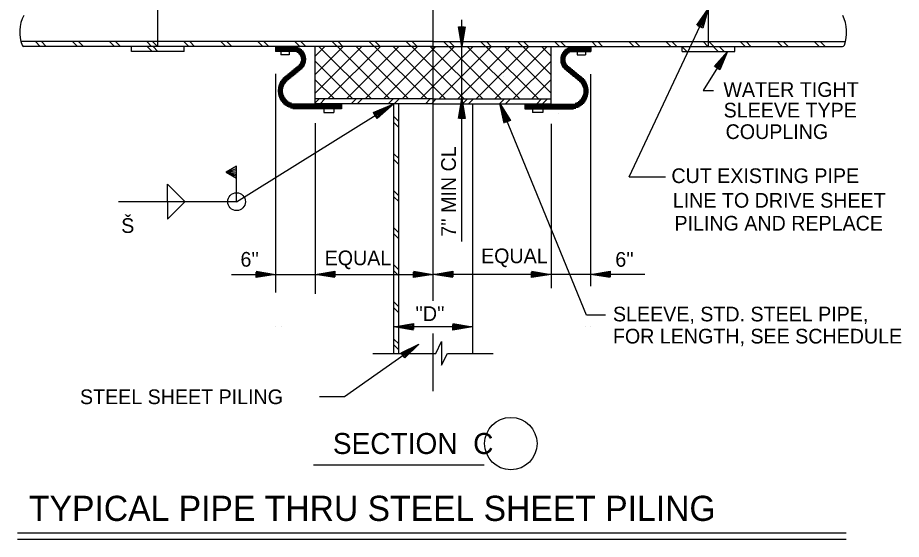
# Model space of a CAD drawing. Extents: x 22411.4 to 22495.4, y 22369.6 to 22415.
# Drawn here: x 22451.27 to 22462.5, y 22382.35 to 22388.98 of the extents above; entities that cross this region are included whole.
import ezdxf

# ---------------------------------------------------------------- set-up
doc = ezdxf.new("R2010")
doc.units = 0
for name, color, linetype in [('Level 1', 7, 'Continuous'), ('Level 10', 7, 'Continuous'), ('Level 2', 7, 'Continuous'), ('Level 3', 7, 'Continuous'), ('Level 4', 7, 'Continuous'), ('Level 8', 7, 'Continuous')]:
    doc.layers.add(name, color=color, linetype=linetype)

msp = doc.modelspace()

# ---------------------------------------------------------------- linework, layer by layer
at = {"layer": 'Level 1'}
for p, q in [((22456.549, 22385.383), (22456.549, 22394.627)), ((22456.914, 22388.617), (22456.914, 22388.955)), ((22456.914, 22388.686), (22456.914, 22388.686)), ((22456.914, 22387.95), (22456.914, 22388.617)), ((22456.914, 22388.617), (22456.914, 22388.617)), ((22454.614, 22388.555), (22454.614, 22388.512)), ((22454.718, 22388.512), (22454.614, 22388.512)), ((22454.718, 22388.555), (22454.718, 22388.512)), ((22458.381, 22388.555), (22458.381, 22388.512)), ((22458.381, 22388.512), (22458.485, 22388.512)), ((22458.485, 22388.555), (22458.485, 22388.512)), ((22460.252, 22388.496), (22460.252, 22388.496)), ((22460.289, 22388.555), (22460.289, 22388.555)), ((22454.547, 22388.268), (22454.547, 22385.49)), ((22455.996, 22388.26), (22455.996, 22388.26)), ((22457.441, 22388.23), (22457.441, 22388.23)), ((22458.549, 22388.265), (22458.549, 22385.57)), ((22456.049, 22387.888), (22456.049, 22387.888)), ((22456.914, 22386.137), (22456.914, 22387.95)), ((22456.914, 22387.95), (22456.914, 22387.95)), ((22455.158, 22387.826), (22455.158, 22387.779)), ((22455.158, 22387.779), (22455.286, 22387.779)), ((22455.286, 22387.826), (22455.286, 22387.779)), ((22456.914, 22387.881), (22456.914, 22387.881)), ((22457.417, 22387.878), (22457.417, 22387.878)), ((22457.813, 22387.826), (22457.813, 22387.779)), ((22457.941, 22387.779), (22457.813, 22387.779)), ((22457.941, 22387.826), (22457.941, 22387.779)), ((22458.136, 22387.834), (22458.136, 22387.834)), ((22458.144, 22387.765), (22458.144, 22387.765)), ((22455.049, 22387.643), (22455.049, 22385.472)), ((22458.049, 22387.635), (22458.049, 22385.543)), ((22453.984, 22385.719), (22454.547, 22385.719)), ((22454.547, 22385.719), (22455.049, 22385.719)), ((22455.049, 22385.719), (22455.049, 22385.719)), ((22455.049, 22385.719), (22456.549, 22385.719)), ((22455.119, 22385.719), (22455.119, 22385.719)), ((22456.48, 22385.719), (22456.48, 22385.719)), ((22456.549, 22385.719), (22456.549, 22385.719)), ((22456.549, 22385.719), (22456.549, 22385.719)), ((22458.049, 22385.719), (22456.549, 22385.719)), ((22456.619, 22385.719), (22456.619, 22385.719)), ((22457.98, 22385.719), (22457.98, 22385.719)), ((22458.049, 22385.719), (22458.049, 22385.719)), ((22458.549, 22385.719), (22458.049, 22385.719)), ((22459.24, 22385.719), (22458.549, 22385.719)), ((22454.547, 22385.053), (22454.547, 22385.053)), ((22454.617, 22385.053), (22454.617, 22385.053)), ((22457.049, 22385.053), (22456.049, 22385.053)), ((22456.48, 22385.053), (22456.48, 22385.053)), ((22456.549, 22385.053), (22456.549, 22385.053)), ((22456.549, 22385.053), (22456.549, 22385.053)), ((22456.549, 22384.235), (22456.549, 22384.97)), ((22456.619, 22385.053), (22456.619, 22385.053)), ((22458.48, 22385.053), (22458.48, 22385.053)), ((22458.549, 22385.053), (22458.549, 22385.053)), ((22456.312, 22384.794), (22456.312, 22384.794)), ((22456.369, 22384.834), (22456.369, 22384.834)), ((22455.783, 22384.715), (22456.581, 22384.715)), ((22456.731, 22384.715), (22457.311, 22384.715))]:
    msp.add_line(p, q, dxfattribs=at)
for points in [[(22456.955, 22388.866), (22456.914, 22388.617), (22456.873, 22388.866), (22456.943, 22388.866), (22456.914, 22388.686), (22456.886, 22388.856), (22456.931, 22388.856), (22456.914, 22388.753), (22456.899, 22388.845), (22456.918, 22388.845), (22456.914, 22388.822)], [(22456.873, 22387.701), (22456.914, 22387.95), (22456.955, 22387.701), (22456.885, 22387.701), (22456.914, 22387.881), (22456.942, 22387.712), (22456.897, 22387.712), (22456.914, 22387.814), (22456.929, 22387.722), (22456.91, 22387.722), (22456.914, 22387.745)], [(22456.581, 22384.715), (22456.656, 22384.865), (22456.656, 22384.565), (22456.731, 22384.715)]]:
    msp.add_lwpolyline(points, dxfattribs=at)
for centre, radius, start, end in [((22451.774, 22388.798), 0.48, 153.3929, 200.1919), ((22461.325, 22388.798), 0.48, 339.8081, 26.6071), ((22451.346, 22388.641), 0.0235, 200.3155, 270), ((22461.753, 22388.641), 0.0235, 270, 339.6845)]:
    msp.add_arc(centre, radius, start, end, dxfattribs=at)
at = {"layer": 'Level 10'}
for p, q in [((22454.051, 22386.644), (22456.049, 22387.888)), ((22456.049, 22387.888), (22456.049, 22387.888)), ((22455.983, 22387.847), (22455.983, 22387.847)), ((22454.051, 22387.094), (22453.92, 22387.019)), ((22453.92, 22387.019), (22454.051, 22387.066)), ((22453.92, 22387.019), (22454.051, 22387.04)), ((22453.92, 22387.019), (22454.05, 22386.944)), ((22453.92, 22387.019), (22454.043, 22387.012)), ((22453.92, 22387.019), (22454.048, 22386.989)), ((22453.92, 22387.019), (22454.051, 22386.968)), ((22454.051, 22386.644), (22454.051, 22387.094)), ((22453.172, 22386.866), (22453.395, 22386.643)), ((22453.172, 22386.641), (22453.172, 22386.866)), ((22454.051, 22386.644), (22452.55, 22386.644)), ((22453.172, 22386.646), (22453.172, 22386.421)), ((22453.172, 22386.421), (22453.395, 22386.645)), ((22455.029, 22383.3), (22457.199, 22383.3)), ((22451.268, 22382.434), (22461.797, 22382.434)), ((22451.268, 22382.351), (22461.797, 22382.351))]:
    msp.add_line(p, q, dxfattribs=at)
msp.add_lwpolyline([(22455.787, 22387.779), (22456.049, 22387.888), (22455.836, 22387.7), (22455.794, 22387.768), (22455.983, 22387.847), (22455.838, 22387.719), (22455.811, 22387.763), (22455.92, 22387.807), (22455.84, 22387.738), (22455.829, 22387.756), (22455.853, 22387.766)], dxfattribs=at)
msp.add_circle((22454.051, 22386.644), 0.113, dxfattribs=at)
at = {"layer": 'Level 2'}
for p, q in [((22453.049, 22388.617), (22453.049, 22389.409)), ((22460.049, 22388.617), (22460.049, 22389.409)), ((22459.039, 22386.96), (22460.044, 22389.095)), ((22456.549, 22388.68), (22451.309, 22388.68)), ((22456.549, 22388.68), (22461.79, 22388.68)), ((22456.549, 22388.617), (22451.346, 22388.617)), ((22452.716, 22388.555), (22452.716, 22388.617)), ((22453.383, 22388.555), (22453.383, 22388.617)), ((22454.546, 22388.617), (22454.546, 22388.555)), ((22454.707, 22388.622), (22454.707, 22388.617)), ((22455.049, 22387.888), (22455.049, 22388.617)), ((22456.549, 22388.617), (22461.753, 22388.617)), ((22458.049, 22387.888), (22458.049, 22388.617)), ((22458.553, 22388.617), (22458.553, 22388.555)), ((22459.716, 22388.555), (22459.716, 22388.617)), ((22460.383, 22388.555), (22460.383, 22388.617)), ((22453.383, 22388.555), (22452.716, 22388.555)), ((22454.811, 22388.555), (22454.546, 22388.555)), ((22458.288, 22388.555), (22458.553, 22388.555)), ((22459.716, 22388.555), (22460.383, 22388.555)), ((22460.289, 22388.555), (22459.979, 22388.056)), ((22459.979, 22388.056), (22460.111, 22388.056)), ((22456.549, 22387.95), (22455.049, 22387.95)), ((22456.549, 22387.888), (22455.049, 22387.888)), ((22455.384, 22387.888), (22455.384, 22387.826)), ((22456.049, 22384.715), (22456.049, 22387.888)), ((22456.112, 22384.715), (22456.112, 22387.888)), ((22456.549, 22387.95), (22458.049, 22387.95)), ((22456.549, 22387.888), (22458.049, 22387.888)), ((22457.049, 22387.888), (22457.049, 22384.715)), ((22457.715, 22387.888), (22457.715, 22387.826)), ((22455.384, 22387.826), (22454.765, 22387.826)), ((22457.715, 22387.826), (22458.334, 22387.826)), ((22459.039, 22386.96), (22459.504, 22386.96))]:
    msp.add_line(p, q, dxfattribs=at)
for points in [[(22459.9, 22388.887), (22460.044, 22389.095), (22459.975, 22388.852), (22459.911, 22388.882), (22460.014, 22389.032), (22459.967, 22388.867), (22459.926, 22388.886), (22459.986, 22388.972), (22459.96, 22388.882), (22459.943, 22388.89), (22459.956, 22388.909)], [(22454.797, 22388.615), (22454.549, 22388.615)], [(22454.831, 22388.605), (22454.549, 22388.605)], [(22454.852, 22388.594), (22454.549, 22388.594)], [(22454.867, 22388.584), (22454.549, 22388.584)], [(22454.88, 22388.573), (22454.549, 22388.573)], [(22454.89, 22388.563), (22454.549, 22388.563)], [(22458.209, 22388.563), (22458.549, 22388.563)], [(22458.219, 22388.573), (22458.549, 22388.573)], [(22458.232, 22388.584), (22458.549, 22388.584)], [(22458.247, 22388.594), (22458.549, 22388.594)], [(22458.267, 22388.605), (22458.549, 22388.605)], [(22458.302, 22388.615), (22458.549, 22388.615)], [(22454.899, 22388.552), (22454.79, 22388.552)], [(22454.906, 22388.542), (22454.817, 22388.542)], [(22454.912, 22388.532), (22454.832, 22388.532)], [(22454.917, 22388.521), (22454.843, 22388.521)], [(22454.922, 22388.511), (22454.852, 22388.511)], [(22454.925, 22388.5), (22454.858, 22388.5)], [(22454.928, 22388.49), (22454.863, 22388.49)], [(22454.93, 22388.48), (22454.867, 22388.48)], [(22454.932, 22388.469), (22454.869, 22388.469)], [(22454.933, 22388.459), (22454.87, 22388.459)], [(22458.166, 22388.459), (22458.229, 22388.459)], [(22458.167, 22388.469), (22458.23, 22388.469)], [(22458.168, 22388.48), (22458.232, 22388.48)], [(22458.171, 22388.49), (22458.236, 22388.49)], [(22458.173, 22388.5), (22458.241, 22388.5)], [(22458.177, 22388.511), (22458.247, 22388.511)], [(22458.181, 22388.521), (22458.256, 22388.521)], [(22458.187, 22388.532), (22458.266, 22388.532)], [(22458.193, 22388.542), (22458.282, 22388.542)], [(22458.2, 22388.552), (22458.308, 22388.552)], [(22460.122, 22388.365), (22460.289, 22388.555), (22460.192, 22388.321), (22460.132, 22388.358), (22460.252, 22388.496), (22460.187, 22388.337), (22460.148, 22388.361), (22460.217, 22388.439), (22460.181, 22388.353), (22460.165, 22388.363), (22460.18, 22388.38)], [(22454.894, 22388.344), (22454.8, 22388.344)], [(22454.902, 22388.355), (22454.813, 22388.355)], [(22454.909, 22388.365), (22454.825, 22388.365)], [(22454.915, 22388.375), (22454.838, 22388.375)], [(22454.92, 22388.386), (22454.847, 22388.386)], [(22454.924, 22388.396), (22454.855, 22388.396)], [(22454.927, 22388.407), (22454.86, 22388.407)], [(22454.929, 22388.417), (22454.865, 22388.417)], [(22454.931, 22388.427), (22454.868, 22388.427)], [(22454.933, 22388.448), (22454.87, 22388.448)], [(22454.932, 22388.438), (22454.87, 22388.438)], [(22458.166, 22388.448), (22458.228, 22388.448)], [(22458.166, 22388.438), (22458.229, 22388.438)], [(22458.168, 22388.427), (22458.231, 22388.427)], [(22458.169, 22388.417), (22458.234, 22388.417)], [(22458.172, 22388.407), (22458.238, 22388.407)], [(22458.175, 22388.396), (22458.244, 22388.396)], [(22458.179, 22388.386), (22458.251, 22388.386)], [(22458.184, 22388.375), (22458.261, 22388.375)], [(22458.19, 22388.365), (22458.273, 22388.365)], [(22458.197, 22388.355), (22458.286, 22388.355)], [(22458.205, 22388.344), (22458.299, 22388.344)], [(22454.758, 22388.23), (22454.66, 22388.23)], [(22454.771, 22388.24), (22454.672, 22388.24)], [(22454.784, 22388.25), (22454.685, 22388.25)], [(22454.797, 22388.261), (22454.698, 22388.261)], [(22454.809, 22388.271), (22454.711, 22388.271)], [(22454.822, 22388.282), (22454.723, 22388.282)], [(22454.835, 22388.292), (22454.736, 22388.292)], [(22454.848, 22388.302), (22454.749, 22388.302)], [(22454.86, 22388.313), (22454.762, 22388.313)], [(22454.873, 22388.323), (22454.774, 22388.323)], [(22454.885, 22388.334), (22454.787, 22388.334)], [(22458.214, 22388.334), (22458.312, 22388.334)], [(22458.226, 22388.323), (22458.325, 22388.323)], [(22458.238, 22388.313), (22458.337, 22388.313)], [(22458.251, 22388.302), (22458.35, 22388.302)], [(22458.264, 22388.292), (22458.363, 22388.292)], [(22458.277, 22388.282), (22458.376, 22388.282)], [(22458.289, 22388.271), (22458.388, 22388.271)], [(22458.302, 22388.261), (22458.401, 22388.261)], [(22458.315, 22388.25), (22458.414, 22388.25)], [(22458.328, 22388.24), (22458.427, 22388.24)], [(22458.341, 22388.23), (22458.439, 22388.23)], [(22454.65, 22388.115), (22454.584, 22388.115)], [(22454.655, 22388.125), (22454.588, 22388.125)], [(22454.661, 22388.136), (22454.591, 22388.136)], [(22454.667, 22388.146), (22454.596, 22388.146)], [(22454.675, 22388.157), (22454.601, 22388.157)], [(22454.684, 22388.167), (22454.606, 22388.167)], [(22454.695, 22388.177), (22454.613, 22388.177)], [(22454.707, 22388.188), (22454.62, 22388.188)], [(22454.72, 22388.198), (22454.628, 22388.198)], [(22454.733, 22388.209), (22454.637, 22388.209)], [(22454.746, 22388.219), (22454.648, 22388.219)], [(22458.353, 22388.219), (22458.451, 22388.219)], [(22458.366, 22388.209), (22458.462, 22388.209)], [(22458.379, 22388.198), (22458.471, 22388.198)], [(22458.392, 22388.188), (22458.479, 22388.188)], [(22458.404, 22388.177), (22458.486, 22388.177)], [(22458.415, 22388.167), (22458.492, 22388.167)], [(22458.424, 22388.157), (22458.498, 22388.157)], [(22458.432, 22388.146), (22458.503, 22388.146)], [(22458.438, 22388.136), (22458.507, 22388.136)], [(22458.444, 22388.125), (22458.511, 22388.125)], [(22458.449, 22388.115), (22458.515, 22388.115)], [(22454.639, 22388.063), (22454.576, 22388.063)], [(22454.638, 22388.052), (22454.576, 22388.052)], [(22454.639, 22388.042), (22454.576, 22388.042)], [(22454.64, 22388.073), (22454.577, 22388.073)], [(22454.639, 22388.032), (22454.577, 22388.032)], [(22454.641, 22388.084), (22454.578, 22388.084)], [(22454.641, 22388.021), (22454.578, 22388.021)], [(22454.644, 22388.094), (22454.58, 22388.094)], [(22454.643, 22388.011), (22454.58, 22388.011)], [(22454.647, 22388.105), (22454.582, 22388.105)], [(22454.647, 22388), (22454.582, 22388)], [(22458.452, 22388.105), (22458.517, 22388.105)], [(22458.452, 22388), (22458.517, 22388)], [(22458.455, 22388.094), (22458.519, 22388.094)], [(22458.455, 22388.011), (22458.519, 22388.011)], [(22458.458, 22388.084), (22458.521, 22388.084)], [(22458.458, 22388.021), (22458.521, 22388.021)], [(22458.459, 22388.073), (22458.522, 22388.073)], [(22458.459, 22388.032), (22458.522, 22388.032)], [(22458.46, 22388.063), (22458.523, 22388.063)], [(22458.46, 22388.042), (22458.523, 22388.042)], [(22458.461, 22388.052), (22458.523, 22388.052)], [(22454.65, 22387.99), (22454.584, 22387.99)], [(22454.655, 22387.98), (22454.588, 22387.98)], [(22454.66, 22387.969), (22454.591, 22387.969)], [(22454.667, 22387.959), (22454.596, 22387.959)], [(22454.675, 22387.948), (22454.601, 22387.948)], [(22454.684, 22387.938), (22454.606, 22387.938)], [(22454.695, 22387.927), (22454.613, 22387.927)], [(22454.708, 22387.917), (22454.62, 22387.917)], [(22454.724, 22387.907), (22454.628, 22387.907)], [(22454.747, 22387.896), (22454.637, 22387.896)], [(22458.741, 22385.202), (22458.496, 22385.202), (22457.397, 22387.891)], [(22457.453, 22387.644), (22457.397, 22387.891), (22457.53, 22387.676), (22457.464, 22387.649), (22457.423, 22387.827), (22457.513, 22387.68), (22457.471, 22387.663), (22457.449, 22387.765), (22457.497, 22387.685), (22457.48, 22387.678), (22457.475, 22387.701)], [(22458.352, 22387.896), (22458.462, 22387.896)], [(22458.375, 22387.907), (22458.471, 22387.907)], [(22458.391, 22387.917), (22458.479, 22387.917)], [(22458.404, 22387.927), (22458.486, 22387.927)], [(22458.415, 22387.938), (22458.493, 22387.938)], [(22458.424, 22387.948), (22458.498, 22387.948)], [(22458.432, 22387.959), (22458.503, 22387.959)], [(22458.438, 22387.969), (22458.508, 22387.969)], [(22458.444, 22387.98), (22458.511, 22387.98)], [(22458.449, 22387.99), (22458.515, 22387.99)], [(22455.383, 22387.886), (22454.647, 22387.886)], [(22455.383, 22387.875), (22454.659, 22387.875)], [(22455.383, 22387.865), (22454.673, 22387.865)], [(22455.383, 22387.855), (22454.689, 22387.855)], [(22455.383, 22387.844), (22454.709, 22387.844)], [(22455.383, 22387.834), (22454.736, 22387.834)], [(22457.716, 22387.886), (22458.451, 22387.886)], [(22457.716, 22387.875), (22458.44, 22387.875)], [(22457.716, 22387.865), (22458.426, 22387.865)], [(22457.716, 22387.855), (22458.41, 22387.855)], [(22457.716, 22387.844), (22458.39, 22387.844)], [(22457.716, 22387.834), (22458.363, 22387.834)], [(22454.298, 22385.761), (22454.547, 22385.719), (22454.298, 22385.678), (22454.298, 22385.749), (22454.478, 22385.719), (22454.309, 22385.691), (22454.309, 22385.737), (22454.411, 22385.719), (22454.319, 22385.705), (22454.319, 22385.723), (22454.342, 22385.719)], [(22455.299, 22385.678), (22455.049, 22385.719), (22455.299, 22385.761), (22455.299, 22385.69), (22455.119, 22385.719), (22455.288, 22385.747), (22455.288, 22385.702), (22455.185, 22385.719), (22455.277, 22385.734), (22455.277, 22385.715), (22455.255, 22385.719)], [(22456.3, 22385.761), (22456.549, 22385.719), (22456.3, 22385.678), (22456.3, 22385.749), (22456.48, 22385.719), (22456.311, 22385.691), (22456.311, 22385.737), (22456.413, 22385.719), (22456.321, 22385.705), (22456.321, 22385.723), (22456.344, 22385.719)], [(22456.799, 22385.678), (22456.549, 22385.719), (22456.799, 22385.761), (22456.799, 22385.69), (22456.619, 22385.719), (22456.788, 22385.747), (22456.788, 22385.702), (22456.685, 22385.719), (22456.777, 22385.734), (22456.777, 22385.715), (22456.755, 22385.719)], [(22457.8, 22385.761), (22458.049, 22385.719), (22457.8, 22385.678), (22457.8, 22385.749), (22457.98, 22385.719), (22457.811, 22385.691), (22457.811, 22385.737), (22457.913, 22385.719), (22457.821, 22385.705), (22457.821, 22385.723), (22457.844, 22385.719)], [(22458.799, 22385.678), (22458.549, 22385.719), (22458.799, 22385.761), (22458.799, 22385.69), (22458.619, 22385.719), (22458.788, 22385.747), (22458.788, 22385.702), (22458.685, 22385.719), (22458.777, 22385.734), (22458.777, 22385.715), (22458.755, 22385.719)], [(22456.299, 22385.011), (22456.049, 22385.053), (22456.299, 22385.094), (22456.299, 22385.023), (22456.119, 22385.053), (22456.288, 22385.081), (22456.288, 22385.035), (22456.185, 22385.053), (22456.277, 22385.067), (22456.277, 22385.049), (22456.255, 22385.053)], [(22456.8, 22385.094), (22457.049, 22385.053), (22456.8, 22385.011), (22456.8, 22385.082), (22456.98, 22385.053), (22456.811, 22385.025), (22456.811, 22385.07), (22456.913, 22385.053), (22456.821, 22385.038), (22456.821, 22385.057), (22456.844, 22385.053)], [(22455.103, 22384.166), (22455.424, 22384.166), (22456.369, 22384.834)], [(22456.141, 22384.724), (22456.369, 22384.834), (22456.189, 22384.657), (22456.148, 22384.714), (22456.312, 22384.794), (22456.19, 22384.674), (22456.164, 22384.711), (22456.258, 22384.756), (22456.191, 22384.691), (22456.18, 22384.706), (22456.201, 22384.716)]]:
    msp.add_lwpolyline(points, dxfattribs=at)
at = {"layer": 'Level 3'}
msp.add_circle((22457.536, 22383.568), 0.333, dxfattribs=at)
at = {"layer": 'Level 8'}
for p, q in [((22457.397, 22387.891), (22457.397, 22387.891)), ((22457.423, 22387.827), (22457.423, 22387.827)), ((22454.478, 22385.719), (22454.478, 22385.719)), ((22454.547, 22385.719), (22454.547, 22385.719)), ((22455.049, 22385.719), (22455.049, 22385.719)), ((22455.119, 22385.719), (22455.119, 22385.719)), ((22456.48, 22385.719), (22456.48, 22385.719)), ((22456.549, 22385.719), (22456.549, 22385.719)), ((22456.549, 22385.719), (22456.549, 22385.719)), ((22456.619, 22385.719), (22456.619, 22385.719)), ((22457.98, 22385.719), (22457.98, 22385.719)), ((22458.049, 22385.719), (22458.049, 22385.719)), ((22458.549, 22385.719), (22458.549, 22385.719)), ((22458.619, 22385.719), (22458.619, 22385.719)), ((22456.049, 22385.053), (22456.049, 22385.053)), ((22456.119, 22385.053), (22456.119, 22385.053)), ((22456.98, 22385.053), (22456.98, 22385.053)), ((22457.049, 22385.053), (22457.049, 22385.053))]:
    msp.add_line(p, q, dxfattribs=at)
for points in [[(22451.556, 22388.617), (22451.494, 22388.68)], [(22451.631, 22388.617), (22451.569, 22388.68)], [(22452.027, 22388.617), (22451.965, 22388.68)], [(22452.103, 22388.617), (22452.04, 22388.68)], [(22452.499, 22388.617), (22452.436, 22388.68)], [(22452.574, 22388.617), (22452.512, 22388.68)], [(22452.97, 22388.617), (22452.908, 22388.68)], [(22453.046, 22388.617), (22452.983, 22388.68)], [(22453.442, 22388.617), (22453.379, 22388.68)], [(22453.517, 22388.617), (22453.455, 22388.68)], [(22453.913, 22388.617), (22453.851, 22388.68)], [(22453.989, 22388.617), (22453.926, 22388.68)], [(22454.384, 22388.617), (22454.322, 22388.68)], [(22454.46, 22388.617), (22454.397, 22388.68)], [(22454.856, 22388.617), (22454.793, 22388.68)], [(22454.931, 22388.617), (22454.869, 22388.68)], [(22455.327, 22388.617), (22455.265, 22388.68)], [(22455.403, 22388.617), (22455.34, 22388.68)], [(22455.799, 22388.617), (22455.736, 22388.68)], [(22455.874, 22388.617), (22455.812, 22388.68)], [(22456.27, 22388.617), (22456.208, 22388.68)], [(22456.346, 22388.617), (22456.283, 22388.68)], [(22456.742, 22388.617), (22456.679, 22388.68)], [(22456.817, 22388.617), (22456.754, 22388.68)], [(22457.213, 22388.617), (22457.15, 22388.68)], [(22457.288, 22388.617), (22457.226, 22388.68)], [(22457.684, 22388.617), (22457.622, 22388.68)], [(22457.76, 22388.617), (22457.697, 22388.68)], [(22458.156, 22388.617), (22458.093, 22388.68)], [(22458.231, 22388.617), (22458.169, 22388.68)], [(22458.627, 22388.617), (22458.565, 22388.68)], [(22458.703, 22388.617), (22458.64, 22388.68)], [(22459.099, 22388.617), (22459.036, 22388.68)], [(22459.174, 22388.617), (22459.111, 22388.68)], [(22459.57, 22388.617), (22459.507, 22388.68)], [(22459.645, 22388.617), (22459.583, 22388.68)], [(22460.041, 22388.617), (22459.979, 22388.68)], [(22460.117, 22388.617), (22460.054, 22388.68)], [(22460.513, 22388.617), (22460.45, 22388.68)], [(22460.588, 22388.617), (22460.526, 22388.68)], [(22460.984, 22388.617), (22460.922, 22388.68)], [(22461.06, 22388.617), (22460.997, 22388.68)], [(22461.456, 22388.617), (22461.393, 22388.68)], [(22461.531, 22388.617), (22461.468, 22388.68)], [(22452.976, 22388.555), (22452.914, 22388.617)], [(22453.051, 22388.555), (22452.989, 22388.617)], [(22455.049, 22388.024), (22455.642, 22388.617)], [(22455.049, 22388.26), (22455.407, 22388.617)], [(22455.049, 22388.496), (22455.171, 22388.617)], [(22455.764, 22387.95), (22455.098, 22388.617)], [(22455.211, 22387.95), (22455.878, 22388.617)], [(22456, 22387.95), (22455.333, 22388.617)], [(22455.447, 22387.95), (22456.114, 22388.617)], [(22456.236, 22387.95), (22455.569, 22388.617)], [(22455.683, 22387.95), (22456.35, 22388.617)], [(22456.471, 22387.95), (22455.805, 22388.617)], [(22455.919, 22387.95), (22456.585, 22388.617)], [(22456.707, 22387.95), (22456.04, 22388.617)], [(22456.154, 22387.95), (22456.821, 22388.617)], [(22456.943, 22387.95), (22456.276, 22388.617)], [(22456.39, 22387.95), (22457.057, 22388.617)], [(22457.179, 22387.95), (22456.512, 22388.617)], [(22456.626, 22387.95), (22457.292, 22388.617)], [(22457.414, 22387.95), (22456.748, 22388.617)], [(22456.861, 22387.95), (22457.528, 22388.617)], [(22457.65, 22387.95), (22456.983, 22388.617)], [(22457.097, 22387.95), (22457.764, 22388.617)], [(22457.886, 22387.95), (22457.219, 22388.617)], [(22457.333, 22387.95), (22457.999, 22388.617)], [(22458.049, 22388.022), (22457.455, 22388.617)], [(22458.049, 22388.258), (22457.69, 22388.617)], [(22458.049, 22388.494), (22457.926, 22388.617)], [(22459.774, 22388.555), (22459.716, 22388.613)], [(22460.17, 22388.555), (22460.108, 22388.617)], [(22460.246, 22388.555), (22460.183, 22388.617)], [(22455.528, 22387.95), (22455.049, 22388.43)], [(22457.568, 22387.95), (22458.049, 22388.431)], [(22455.293, 22387.95), (22455.049, 22388.194)], [(22457.804, 22387.95), (22458.049, 22388.196)], [(22455.049, 22387.901), (22455.099, 22387.95)], [(22455.112, 22387.888), (22455.174, 22387.95)], [(22455.508, 22387.888), (22455.57, 22387.95)], [(22455.583, 22387.888), (22455.645, 22387.95)], [(22455.979, 22387.888), (22456.041, 22387.95)], [(22456.054, 22387.888), (22456.117, 22387.95)], [(22456.45, 22387.888), (22456.513, 22387.95)], [(22456.526, 22387.888), (22456.588, 22387.95)], [(22456.922, 22387.888), (22456.984, 22387.95)], [(22456.997, 22387.888), (22457.06, 22387.95)], [(22457.393, 22387.888), (22457.456, 22387.95)], [(22457.469, 22387.888), (22457.531, 22387.95)], [(22457.865, 22387.888), (22457.927, 22387.95)], [(22457.94, 22387.888), (22458.002, 22387.95)], [(22456.112, 22387.663), (22456.049, 22387.726)], [(22456.112, 22387.588), (22456.049, 22387.65)], [(22456.112, 22387.192), (22456.049, 22387.254)], [(22456.112, 22387.116), (22456.049, 22387.179)], [(22456.112, 22386.72), (22456.049, 22386.783)], [(22456.112, 22386.645), (22456.049, 22386.707)], [(22456.112, 22386.249), (22456.049, 22386.311)], [(22456.112, 22386.173), (22456.049, 22386.236)], [(22456.112, 22385.777), (22456.049, 22385.84)], [(22456.112, 22385.702), (22456.049, 22385.764)], [(22456.112, 22385.306), (22456.049, 22385.369)], [(22456.112, 22385.231), (22456.049, 22385.293)], [(22456.112, 22384.835), (22456.049, 22384.897)], [(22456.112, 22384.759), (22456.049, 22384.822)]]:
    msp.add_lwpolyline(points, dxfattribs=at)

# ---------------------------------------------------------------- texts
at = {"layer": 'Level 3'}
for s, height, p in [('SECTION  C', 0.2667, (22455.274, 22383.436)), ('TYPICAL PIPE THRU STEEL SHEET PILING', 0.32, (22451.412, 22382.585))]:
    msp.add_text(s, height=height, dxfattribs=at).set_placement(p)
at = {"layer": 'Level 4'}
for s, height, p in [('WATER TIGHT', 0.18667, (22460.238, 22387.977)), ('SLEEVE TYPE', 0.18667, (22460.241, 22387.715)), ('COUPLING', 0.1867, (22460.266, 22387.441)), ('CUT EXISTING PIPE', 0.18667, (22459.577, 22386.881)), ('LINE TO DRIVE SHEET', 0.18667, (22459.595, 22386.568)), ('Š', 0.187, (22452.584, 22386.247)), ('PILING AND REPLACE', 0.18667, (22459.616, 22386.277)), ("6''", 0.1867, (22454.1, 22385.818)), ('EQUAL', 0.1867, (22455.17, 22385.836)), ('EQUAL', 0.1867, (22457.158, 22385.862)), ("6''", 0.1867, (22458.864, 22385.817)), ("''D''", 0.1867, (22456.323, 22385.127)), ('SLEEVE, STD. STEEL PIPE,', 0.18667, (22458.834, 22385.122)), ('FOR LENGTH, SEE SCHEDULE', 0.18667, (22458.834, 22384.841)), ('STEEL SHEET PILING', 0.18667, (22452.06, 22384.07))]:
    msp.add_text(s, height=height, dxfattribs=at).set_placement(p)
msp.add_text("7'' MIN CL", height=0.1867, rotation=90, dxfattribs=at).set_placement((22456.838, 22386.198))

doc.saveas('drawing.dxf')
